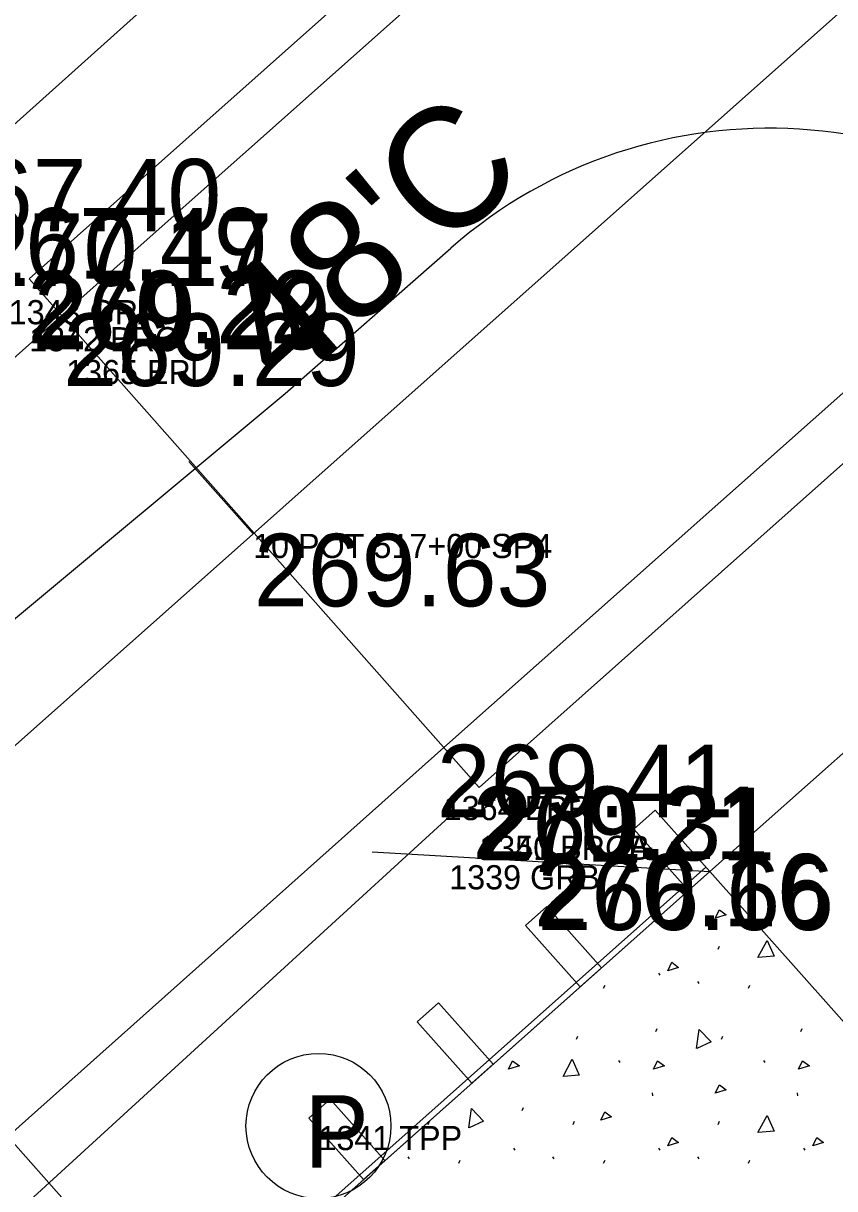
# Model space of a CAD drawing. Extents: x 49683 to 58852, y 49525 to 54803.
# Drawn here: x 53432.32 to 53465.9, y 51453.56 to 51501.77 of the extents above; entities that cross this region are included whole.
import ezdxf

# ---------------------------------------------------------------- set-up
doc = ezdxf.new("R2010")
doc.units = 0
for name, color, linetype in [('Level 1', 7, 'Continuous'), ('Level 11', 7, 'Continuous'), ('Level 15', 7, 'Continuous'), ('Level 18', 7, 'Continuous'), ('Level 27', 7, 'Continuous'), ('Level 3', 7, 'Continuous'), ('Level 32', 7, 'Continuous'), ('Level 48', 7, 'Continuous'), ('Level 5', 7, 'Continuous'), ('Level 51', 7, 'Continuous'), ('Level 53', 7, 'Continuous'), ('Level 55', 7, 'Continuous'), ('Level 57', 7, 'Continuous'), ('Level 59', 7, 'Continuous'), ('Level 7', 7, 'Continuous'), ('Level 8', 7, 'Continuous'), ('Level 9', 7, 'Continuous')]:
    doc.layers.add(name, color=color, linetype=linetype)

# ---------------------------------------------------------------- blocks, each defined once
blk = doc.blocks.new('TPP')
at = {"layer": 'Level 9'}
blk.add_circle((0, 0), 3, dxfattribs=at)
blk.add_text('P', height=3, dxfattribs=at).set_placement((-0.589, -1.729))

msp = doc.modelspace()

# ---------------------------------------------------------------- linework, layer by layer
at = {"layer": 'Level 1'}
for p, q in [((52544.807, 50683.302), (55534.583, 53340.862)), ((53441.831, 51480.651), (53439.174, 51483.64))]:
    msp.add_line(p, q, dxfattribs=at)
at = {"layer": 'Level 11'}
msp.add_line((53424.495, 51490.929), (53894.91, 51911.927), dxfattribs=at)
at = {"layer": 'Level 15'}
for p, q in [((53460.734, 51466.679), (53909.18, 51865.296)), ((53446.758, 51467.502), (53460.734, 51466.679)), ((53445.785, 51453.392), (53460.734, 51466.679)), ((53460.734, 51466.679), (53489.966, 51433.793)), ((53461.076, 51463.466), (53461.131, 51463.591)), ((53458.608, 51462.481), (53458.663, 51462.398)), ((53456.338, 51461.856), (53456.394, 51461.981)), ((53460.227, 51462.128), (53460.282, 51462.045)), ((53462.338, 51461.856), (53462.394, 51461.981)), ((53458.503, 51460.066), (53458.558, 51460.191)), ((53464.503, 51460.066), (53464.558, 51460.191)), ((53455.214, 51459.747), (53455.27, 51459.872)), ((53461.214, 51459.747), (53461.27, 51459.872)), ((53456.949, 51458.859), (53457.004, 51458.776)), ((53462.949, 51458.859), (53463.004, 51458.776)), ((53458.351, 51457.528), (53458.365, 51457.403)), ((53464.351, 51457.528), (53464.365, 51457.403)), ((53452.967, 51456.792), (53453.022, 51456.917)), ((53449.076, 51456.223), (53449.131, 51456.348)), ((53455.076, 51456.223), (53455.131, 51456.348)), ((53461.076, 51456.223), (53461.131, 51456.348)), ((53452.608, 51455.238), (53452.663, 51455.155)), ((53458.608, 51455.238), (53458.663, 51455.155)), ((53464.608, 51455.238), (53464.663, 51455.155)), ((53448.227, 51454.885), (53448.282, 51454.802)), ((53450.338, 51454.614), (53450.394, 51454.738)), ((53454.227, 51454.885), (53454.282, 51454.802)), ((53456.338, 51454.614), (53456.394, 51454.738)), ((53460.227, 51454.885), (53460.282, 51454.802)), ((53462.338, 51454.614), (53462.394, 51454.738))]:
    msp.add_line(p, q, dxfattribs=at)
for points in [[(53460.959, 51464.75), (53461.126, 51465.096), (53461.403, 51464.888), (53460.959, 51464.75)], [(53462.724, 51463.124), (53463.099, 51463.831), (53463.39, 51463.179), (53462.738, 51463.124)], [(53458.994, 51462.578), (53459.161, 51462.925), (53459.438, 51462.716), (53458.994, 51462.578)], [(53460.174, 51459.36), (53460.284, 51460.153), (53460.781, 51459.64), (53460.187, 51459.364)], [(53452.406, 51458.499), (53452.572, 51458.846), (53452.85, 51458.637), (53452.406, 51458.499)], [(53454.663, 51458.209), (53455.037, 51458.916), (53455.329, 51458.264), (53454.676, 51458.209)], [(53458.406, 51458.499), (53458.572, 51458.846), (53458.85, 51458.637), (53458.406, 51458.499)], [(53464.406, 51458.499), (53464.572, 51458.846), (53464.85, 51458.637), (53464.406, 51458.499)], [(53460.959, 51457.507), (53461.126, 51457.854), (53461.403, 51457.646), (53460.959, 51457.507)], [(53450.764, 51456.08), (53450.874, 51456.873), (53451.371, 51456.359), (53450.777, 51456.084)], [(53456.219, 51456.393), (53456.385, 51456.74), (53456.663, 51456.532), (53456.219, 51456.393)], [(53462.724, 51455.881), (53463.099, 51456.589), (53463.39, 51455.937), (53462.738, 51455.881)], [(53458.994, 51455.335), (53459.161, 51455.682), (53459.438, 51455.474), (53458.994, 51455.335)], [(53464.994, 51455.335), (53465.161, 51455.682), (53465.438, 51455.474), (53464.994, 51455.335)]]:
    msp.add_lwpolyline(points, dxfattribs=at)
at = {"layer": 'Level 18'}
for p, q in [((53443.152, 51486.459), (53450.017, 51492.472)), ((53395.485, 51446.762), (53443.152, 51486.459))]:
    msp.add_line(p, q, dxfattribs=at)
msp.add_arc((53463.195, 51477.428), 20, 41.6334, 131.2163, dxfattribs=at)
at = {"layer": 'Level 27'}
for p, q in [((53457.592, 51468.436), (53458.475, 51469.221)), ((53458.475, 51469.221), (53460.734, 51466.679)), ((53459.85, 51465.894), (53457.592, 51468.436)), ((53418.518, 51429.489), (53460.568, 51466.866)), ((53418.684, 51429.302), (53460.734, 51466.679)), ((53460.734, 51466.679), (53459.85, 51465.894)), ((53453.107, 51464.45), (53453.991, 51465.235)), ((53453.991, 51465.235), (53456.249, 51462.693)), ((53455.366, 51461.908), (53453.107, 51464.45)), ((53456.249, 51462.693), (53455.366, 51461.908)), ((53448.623, 51460.464), (53449.506, 51461.249)), ((53449.506, 51461.249), (53451.765, 51458.707)), ((53450.881, 51457.922), (53448.623, 51460.464)), ((53451.765, 51458.707), (53450.881, 51457.922)), ((53444.138, 51456.477), (53445.022, 51457.262)), ((53445.022, 51457.262), (53447.28, 51454.721)), ((53446.397, 51453.936), (53444.138, 51456.477)), ((53447.28, 51454.721), (53446.397, 51453.936))]:
    msp.add_line(p, q, dxfattribs=at)
at = {"layer": 'Level 3'}
for p, q in [((53434.092, 51489.844), (53883.273, 51889.178)), ((53449.718, 51471.806), (53898.742, 51870.567)), ((53162.497, 51248.316), (53434.092, 51489.844)), ((53179.352, 51230.724), (53449.718, 51471.806))]:
    msp.add_line(p, q, dxfattribs=at)
at = {"layer": 'Level 5'}
for p, q in [((53432.563, 51491.203), (53881.993, 51890.68)), ((53900.074, 51869.402), (53451.19, 51470.163)), ((53451.19, 51470.163), (53432.563, 51491.203))]:
    msp.add_line(p, q, dxfattribs=at)
at = {"layer": 'Level 7'}
msp.add_line((53424.8, 51445.953), (53449.946, 51468.944), dxfattribs=at)
at = {"layer": 'Level 8'}
msp.add_line((53439.059, 51447.413), (53429.719, 51457.92), dxfattribs=at)

# ---------------------------------------------------------------- block references
at = {"layer": 'Level 9'}
msp.add_blockref('TPP', (53444.535, 51456.156), dxfattribs=at)

# ---------------------------------------------------------------- texts
at = {"layer": 'Level 32'}
for s, p in [('267.40', (53428.244, 51493.16)), ('267.49', (53430.166, 51491.13)), ('270.17', (53430.349, 51490.907)), ('270.22', (53432.485, 51488.533)), ('269.29', (53432.76, 51488.284)), ('269.29', (53433.972, 51486.767)), ('269.63', (53441.864, 51477.651)), ('269.41', (53449.432, 51468.924)), ('270.21', (53450.906, 51467.197)), ('269.31', (53451.16, 51467.144)), ('270.16', (53453.467, 51464.409)), ('266.66', (53453.602, 51464.261))]:
    msp.add_text(s, height=3, dxfattribs=at).set_placement(p)
at = {"layer": 'Level 48'}
msp.add_text("48'C", height=5, rotation=41.6334, dxfattribs=at).set_placement((53443.152, 51486.459))
at = {"layer": 'Level 51'}
msp.add_text('10 POT 517+00 SP4', height=1, dxfattribs=at).set_placement((53441.83, 51479.65))
at = {"layer": 'Level 53'}
for s, p in [('1365 EPL', (53434.092, 51486.844)), ('1364 EPR', (53449.718, 51468.806))]:
    msp.add_text(s, height=1, dxfattribs=at).set_placement(p)
at = {"layer": 'Level 55'}
for s, p in [('1342 BRC', (53432.563, 51488.203)), ('1340 BRCA', (53451.19, 51467.163)), ('1351 BRCB', (53451.19, 51467.163))]:
    msp.add_text(s, height=1, dxfattribs=at).set_placement(p)
at = {"layer": 'Level 57'}
for s, p in [('1343 GRA', (53431.716, 51489.319)), ('1339 GRB', (53449.946, 51465.944))]:
    msp.add_text(s, height=1, dxfattribs=at).set_placement(p)
at = {"layer": 'Level 59'}
msp.add_text('1341 TPP', height=1, dxfattribs=at).set_placement((53444.535, 51455.156))

doc.saveas('drawing.dxf')
